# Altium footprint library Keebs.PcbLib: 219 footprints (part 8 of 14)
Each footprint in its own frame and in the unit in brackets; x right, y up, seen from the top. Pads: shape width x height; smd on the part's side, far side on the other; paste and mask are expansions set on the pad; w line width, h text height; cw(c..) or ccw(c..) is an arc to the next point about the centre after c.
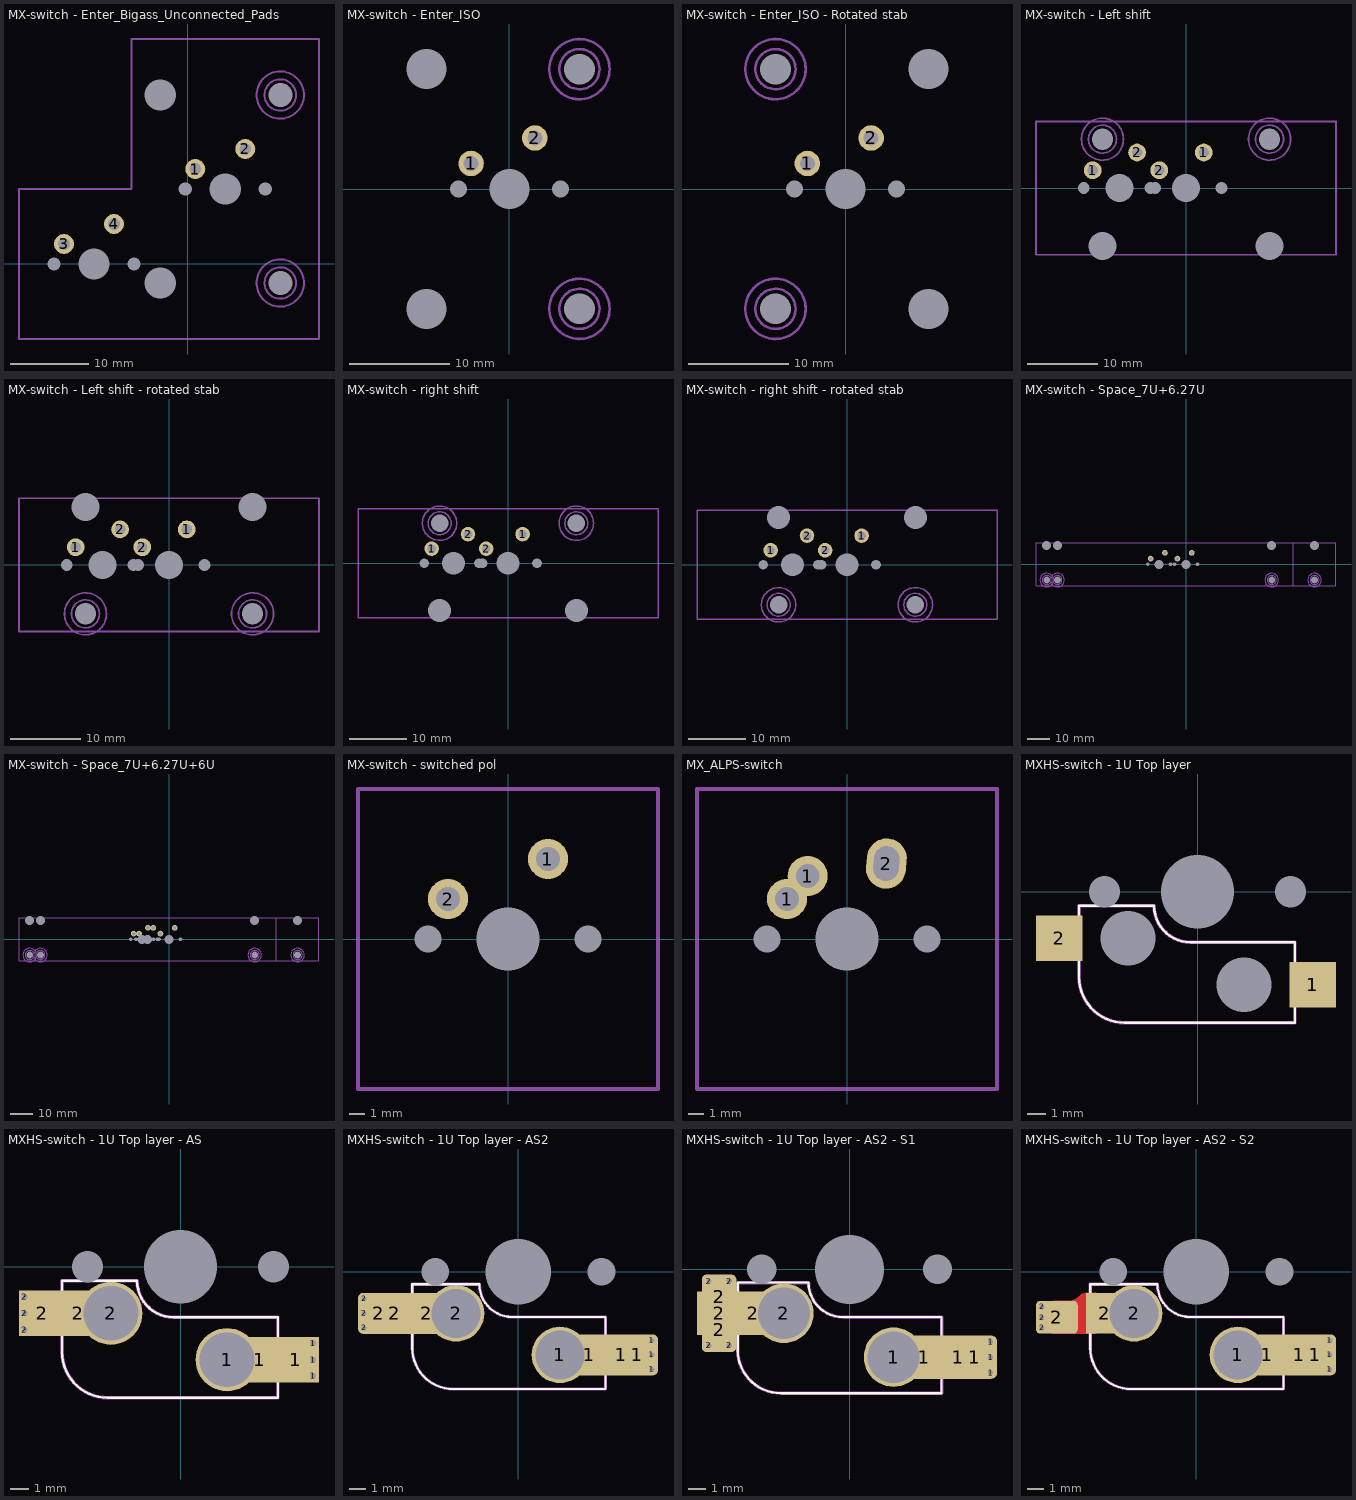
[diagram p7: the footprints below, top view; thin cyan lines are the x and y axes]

## MX-switch - Enter_Bigass_Unconnected_Pads [mm]
pads (20):
  round 2.54 hole 1.5 mask-0.5: 1(0.953,12.065) 2(7.302,14.605) 3(-15.716,2.54) 4(-9.366,5.08)
  round 1 hole 1.7 unplated: ""(-16.986,0) ""(-6.826,0) ""(-0.318,9.525) ""(9.842,9.525)
  round 1 hole 4 unplated: ""(-11.906,0) ""(4.763,9.525)
  round 1 on Mech13: ""(-11.906,0) ""(-11.906,0) ""(0,0) ""(0,0) ""(4.763,9.525) ""(4.763,9.525)
  round 1.524 hole 4 unplated: ""(-3.492,-2.413) ""(-3.492,21.463)
  round 1.524 hole 3.048 unplated: ""(11.747,-2.413) ""(11.747,21.463)
Mechanical 13:
  lines w0.254: -21.431,-9.525 -21.431,9.525 -7.144,9.525 -7.144,28.575 16.669,28.575 16.669,-9.525 -21.431,-9.525
  text ".Designator" at -3.683,-9.017 h0.7
Mechanical 15:
  circle w0.254: c11.747,21.463 r3
  circle w0.254: c11.747,21.463 r2
  circle w0.254: c11.747,-2.413 r3
  circle w0.254: c11.747,-2.413 r2

## MX-switch - Enter_ISO [mm]
pads (10):
  round 2.54 hole 1.5 mask-0.5: 1(-3.81,2.54) 2(2.54,5.08)
  round 1.524 hole 4 unplated: ""(-8.255,-11.938) ""(-8.255,11.938)
  round 1 hole 1.7 unplated: ""(-5.08,0) ""(5.08,0)
  round 1 hole 4 unplated: ""(0,0)
  round 1 on Mech13: ""(0,0)
  round 1.524 hole 3.048 unplated: ""(6.985,-11.938) ""(6.985,11.938)
Mechanical 13:
  text ".Designator" at -1.68,-7.73 h0.7
Mechanical 15:
  circle w0.254: c6.985,11.938 r3
  circle w0.254: c6.985,11.938 r2
  circle w0.254: c6.985,-11.938 r3
  circle w0.254: c6.985,-11.938 r2

## MX-switch - Enter_ISO - Rotated stab [mm]
pads (10):
  round 2.54 hole 1.5 mask-0.5: 1(-3.81,2.54) 2(2.54,5.08)
  round 1.524 hole 3.048 unplated: ""(-6.985,-11.938) ""(-6.985,11.938)
  round 1 hole 1.7 unplated: ""(-5.08,0) ""(5.08,0)
  round 1 hole 4 unplated: ""(0,0)
  round 1 on Mech13: ""(0,0)
  round 1.524 hole 4 unplated: ""(8.255,-11.938) ""(8.255,11.938)
Mechanical 13:
  text ".Designator" at -1.68,-7.73 h0.7
Mechanical 15:
  circle w0.254: c-6.985,-11.938 r3
  circle w0.254: c-6.985,-11.938 r2
  circle w0.254: c-6.985,11.938 r3
  circle w0.254: c-6.985,11.938 r2

## MX-switch - Left shift [mm]
pads (16):
  round 2.54 hole 1.5 mask-0.5: 1(-13.335,2.54) 1(2.54,5.08) 2(-6.985,5.08) 2(-3.81,2.54)
  round 1 hole 1.7 unplated: ""(-14.605,0) ""(-5.08,0) ""(-4.445,0) ""(5.08,0)
  round 1.524 hole 4 unplated: ""(-11.938,-8.255) ""(11.938,-8.255)
  round 1.524 hole 3.048 unplated: ""(-11.938,6.985) ""(11.938,6.985)
  round 1 hole 4 unplated: ""(-9.525,0) ""(0,0)
  round 1 on Mech13: ""(-9.525,0) ""(0,0)
Mechanical 13:
  lines w0.254: -21.431,-9.525 21.431,-9.525 21.431,9.525 -21.431,9.525 -21.431,-9.525
  text ".Designator" at -5.45,-3.925 h0.7
Mechanical 15:
  circle w0.254: c11.938,6.985 r3
  circle w0.254: c11.938,6.985 r2
  circle w0.254: c-11.938,6.985 r3
  circle w0.254: c-11.938,6.985 r2

## MX-switch - Left shift - rotated stab [mm]
pads (16):
  round 2.54 hole 1.5 mask-0.5: 1(-13.335,2.54) 1(2.54,5.08) 2(-6.985,5.08) 2(-3.81,2.54)
  round 1 hole 1.7 unplated: ""(-14.605,0) ""(-5.08,0) ""(-4.445,0) ""(5.08,0)
  round 1.524 hole 3.048 unplated: ""(-11.938,-6.985) ""(11.938,-6.985)
  round 1.524 hole 4 unplated: ""(-11.938,8.255) ""(11.938,8.255)
  round 1 hole 4 unplated: ""(-9.525,0) ""(0,0)
  round 1 on Mech13: ""(-9.525,0) ""(0,0)
Mechanical 13:
  lines w0.254: -21.431,-9.525 -21.431,9.525 21.431,9.525 21.431,-9.525 -21.431,-9.525
  text ".Designator" at -5.45,-3.925 h0.7
Mechanical 15:
  circle w0.254: c-11.938,-6.985 r2
  circle w0.254: c-11.938,-6.985 r3
  circle w0.254: c11.938,-6.985 r2
  circle w0.254: c11.938,-6.985 r3

## MX-switch - right shift [mm]
pads (16):
  round 2.54 hole 1.5 mask-0.5: 1(-13.335,2.54) 1(2.54,5.08) 2(-6.985,5.08) 2(-3.81,2.54)
  round 1 hole 1.7 unplated: ""(-14.605,0) ""(-5.08,0) ""(-4.445,0) ""(5.08,0)
  round 1.524 hole 4 unplated: ""(-11.938,-8.255) ""(11.938,-8.255)
  round 1.524 hole 3.048 unplated: ""(-11.938,6.985) ""(11.938,6.985)
  round 1 hole 4 unplated: ""(-9.525,0) ""(0,0)
  round 1 on Mech13: ""(-9.525,0) ""(0,0)
Mechanical 13:
  lines w0.254: -26.194,-9.525 26.194,-9.525 26.194,9.525 -26.194,9.525 -26.194,-9.525
  text ".Designator" at -4.3,-5.55 h0.7
Mechanical 15:
  circle w0.254: c11.938,6.985 r3
  circle w0.254: c11.938,6.985 r2
  circle w0.254: c-11.938,6.985 r3
  circle w0.254: c-11.938,6.985 r2

## MX-switch - right shift - rotated stab [mm]
pads (16):
  round 2.54 hole 1.5 mask-0.5: 1(-13.335,2.54) 1(2.54,5.08) 2(-6.985,5.08) 2(-3.81,2.54)
  round 1 hole 1.7 unplated: ""(-14.605,0) ""(-5.08,0) ""(-4.445,0) ""(5.08,0)
  round 1.524 hole 3.048 unplated: ""(-11.938,-6.985) ""(11.938,-6.985)
  round 1.524 hole 4 unplated: ""(-11.938,8.255) ""(11.938,8.255)
  round 1 hole 4 unplated: ""(-9.525,0) ""(0,0)
  round 1 on Mech13: ""(-9.525,0) ""(0,0)
Mechanical 13:
  lines w0.254: -26.194,-9.525 -26.194,9.525 26.194,9.525 26.194,-9.525 -26.194,-9.525
  text ".Designator" at -4.3,-5.55 h0.7
Mechanical 15:
  circle w0.254: c11.938,-6.985 r3
  circle w0.254: c11.938,-6.985 r2
  circle w0.254: c-11.938,-6.985 r3
  circle w0.254: c-11.938,-6.985 r2

## MX-switch - Space_7U+6.27U [mm]
pads (20):
  round 2.54 hole 1.5 mask-0.5: 1(-9.366,5.08) 1(-3.81,2.54) 2(-15.716,2.54) 2(2.54,5.08)
  round 1.524 hole 3.048 unplated: ""(-61.91,-6.985) ""(-57.15,-6.985) ""(38.09,-6.985) ""(57.15,-6.985)
  round 1.524 hole 4 unplated: ""(-61.91,8.255) ""(-57.15,8.255) ""(38.09,8.255) ""(57.15,8.255)
  round 1 hole 1.7 unplated: ""(-16.986,0) ""(-6.826,0) ""(-5.08,0) ""(5.08,0)
  round 1 hole 4 unplated: ""(-11.906,0) ""(0,0)
  round 1 on Mech13: ""(-11.906,0) ""(0,0)
Mechanical 13:
  lines w0.254: 47.621,-9.525 47.621,9.525 ; -66.675,-9.525 -66.675,9.525 66.675,9.525 66.675,-9.525 -66.675,-9.525
  text ".Designator" at 7.625,-2.4 h0.7
Mechanical 15:
  circle w0.254: c57.15,-6.985 r3
  circle w0.254: c57.15,-6.985 r2
  circle w0.254: c38.09,-6.985 r3
  circle w0.254: c38.09,-6.985 r2
  circle w0.254: c-57.15,-6.985 r3
  circle w0.254: c-57.15,-6.985 r2
  circle w0.254: c-61.91,-6.985 r3
  circle w0.254: c-61.91,-6.985 r2
  text "7U" at 65.831,-1.85 h1.52
  text "6.25U" at 46.265,-3.6 h1.52

## MX-switch - Space_7U+6.27U+6U [mm]
pads (25):
  round 2.54 hole 1.5 mask-0.5: 1(-9.366,5.08) 1(-6.981,5.08) 1(-3.81,2.54) 2(-15.716,2.54) 2(-13.331,2.54) 2(2.54,5.08)
  round 1.524 hole 3.048 unplated: ""(-61.91,-6.985) ""(-57.15,-6.985) ""(38.09,-6.985) ""(57.15,-6.985)
  round 1.524 hole 4 unplated: ""(-61.91,8.255) ""(-57.15,8.255) ""(38.09,8.255) ""(57.15,8.255)
  round 1 hole 1.7 unplated: ""(-16.986,0) ""(-14.601,0) ""(-6.826,0) ""(-5.08,0) ""(-4.441,0) ""(5.08,0)
  round 1 hole 4 unplated: ""(-11.906,0) ""(-9.521,0) ""(0,0)
  round 1 on Mech13: ""(-11.906,0) ""(0,0)
Mechanical 13:
  lines w0.254: 47.621,-9.525 47.621,9.525 ; -66.675,-9.525 -66.675,9.525 66.675,9.525 66.675,-9.525 -66.675,-9.525
  text ".Designator" at 7.625,-2.4 h0.7
Mechanical 15:
  circle w0.254: c57.15,-6.985 r3
  circle w0.254: c57.15,-6.985 r2
  circle w0.254: c38.09,-6.985 r3
  circle w0.254: c38.09,-6.985 r2
  circle w0.254: c-57.15,-6.985 r3
  circle w0.254: c-57.15,-6.985 r2
  circle w0.254: c-61.91,-6.985 r3
  circle w0.254: c-61.91,-6.985 r2
  text "7U" at 65.831,-1.85 h1.52
  text "6.25U" at 46.265,-3.6 h1.52

## MX-switch - switched pol [mm]
pads (5):
  round 2.54 hole 1.5 mask-0.5: 1(2.54,5.08) 2(-3.81,2.54)
  round 1 hole 1.7 unplated: ""(-5.08,0) ""(5.08,0)
  round 1 hole 4 unplated: ""(0,0)
Mechanical 13:
  lines w0.254: -9.525,-9.525 9.525,-9.525 9.525,9.525 -9.525,9.525 -9.525,-9.525
  text ".Designator" at -3.575,-3.7 h0.7

## MX_ALPS-switch [mm]
pads (6):
  round 2.54 hole 1.5 mask-0.5: 1(-3.81,2.54) 1(-2.5,4)
  oval 3.2x2.54 hole 1.6 slot 2.2 at 85 deg rot 85 mask-1: 2(2.5,4.79)
  round 1 hole 1.7 unplated: ""(-5.08,0) ""(5.08,0)
  round 1 hole 4 unplated: ""(0,0)
Mechanical 13:
  lines w0.254: -9.525,-9.525 9.525,-9.525 9.525,9.525 -9.525,9.525 -9.525,-9.525
  text ".Designator" at -3.575,-3.7 h0.7

## MXHS-switch - 1U Top layer [mm]
pads (7):
  rect 2.55x2.5 smd: 1(6.29,-5.08) 2(-7.56,-2.54)
  round 1 hole 1.7 unplated: ""(-5.08,0) ""(5.08,0)
  round 0 hole 3 unplated: ""(-3.81,-2.54) ""(2.54,-5.08)
  round 1 hole 4 unplated: ""(0,0)
Top Overlay:
  lines w0.127: -6.481,-4.662 ccw(c-3.981,-4.662) -3.981,-7.162 5.319,-7.162 5.319,-2.762 -0.381,-2.762 cw(c-0.381,-0.762) -2.381,-0.762 -6.481,-0.762 -6.481,-4.662
Mechanical 13:
  lines w0.1: -0.5,0 0.5,0 ; 0,-0.5 0,0.5
  lines w0.2: -6.481,-4.662 ccw(c-3.981,-4.662) -3.981,-7.162 5.319,-7.162 5.319,-2.762 -0.381,-2.762 cw(c-0.381,-0.762) -2.381,-0.762 -6.481,-0.762 -6.481,-4.662
  text ".Designator" at 3.048,-4.826 h0.7
Mechanical 15:
  lines w0.1: -1.77,0 -0.77,0 ; 0,-0.5 0,0.5
  lines w0.127: -6.481,-4.662 ccw(c-3.981,-4.662) -3.981,-7.162 5.319,-7.162 5.319,-2.762 -0.381,-2.762 cw(c-0.381,-0.762) -2.381,-0.762 -6.481,-0.762 -6.481,-4.662
3D body "kailh_socket_mx.stp": height -0.35, standoff -3.4, extent -7.9,-6.745 6.6,-0.855

## MXHS-switch - 1U Top layer - AS [mm]
pads (15):
  round 3.45 hole 3 mask+0: 1(2.54,-5.08) 2(-3.81,-2.54)
  rect 2.55x2.5 smd paste-40 mask+0.102: 1(4.318,-5.08) 2(-5.588,-2.54)
  rect 2.55x2.5 smd: 1(6.29,-5.08) 2(-7.56,-2.54)
  round 0.6 hole 0.3 mask+0.102: 1(7.25,-5.969) 1(7.25,-5.08) 1(7.25,-4.191) 2(-8.52,-3.429) 2(-8.52,-2.54) 2(-8.52,-1.651)
  round 1 hole 1.7 unplated: ""(-5.08,0) ""(5.08,0)
  round 1 hole 4 unplated: ""(0,0)
Top Overlay:
  lines w0.127: -6.481,-4.662 ccw(c-3.981,-4.662) -3.981,-7.162 5.319,-7.162 5.319,-2.762 -0.381,-2.762 cw(c-0.381,-0.762) -2.381,-0.762 -6.481,-0.762 -6.481,-4.662
Mechanical 13:
  lines w0.1: -0.5,0 0.5,0 ; 0,-0.5 0,0.5
  lines w0.2: -6.481,-4.662 ccw(c-3.981,-4.662) -3.981,-7.162 5.319,-7.162 5.319,-2.762 -0.381,-2.762 cw(c-0.381,-0.762) -2.381,-0.762 -6.481,-0.762 -6.481,-4.662
  text ".Designator" at 3.048,-4.826 h0.7
Mechanical 15:
  lines w0.1: -1.77,0 -0.77,0 ; 0,-0.5 0,0.5
  lines w0.127: -6.481,-4.662 ccw(c-3.981,-4.662) -3.981,-7.162 5.319,-7.162 5.319,-2.762 -0.381,-2.762 cw(c-0.381,-0.762) -2.381,-0.762 -6.481,-0.762 -6.481,-4.662
3D body "kailh_socket_mx.stp": height -0.35, standoff -3.4, extent -7.9,-6.745 6.6,-0.855

## MXHS-switch - 1U Top layer - AS2 [mm]
pads (17):
  round 3.45 hole 3 mask+0: 1(2.54,-5.08) 2(-3.81,-2.54)
  rect 2.55x2.5 smd paste-40 mask+0.102: 1(4.318,-5.08) 2(-5.588,-2.54)
  rect 2.55x2.5 smd: 1(6.29,-5.08) 2(-7.56,-2.54)
  rrect25% 2.55x2.5 smd paste-40 mask+0.102: 1(7.25,-5.08) 2(-8.52,-2.54)
  round 0.6 hole 0.3 mask+0.102: 1(8.15,-5.969) 1(8.15,-5.08) 1(8.15,-4.191) 2(-9.42,-3.429) 2(-9.42,-2.54) 2(-9.42,-1.651)
  round 1 hole 1.7 unplated: ""(-5.08,0) ""(5.08,0)
  round 1 hole 4 unplated: ""(0,0)
Top Overlay:
  lines w0.127: -6.481,-4.662 ccw(c-3.981,-4.662) -3.981,-7.162 5.319,-7.162 5.319,-2.762 -0.381,-2.762 cw(c-0.381,-0.762) -2.381,-0.762 -6.481,-0.762 -6.481,-4.662
Mechanical 13:
  lines w0.1: -0.5,0 0.5,0 ; 0,-0.5 0,0.5
  lines w0.2: -6.481,-4.662 ccw(c-3.981,-4.662) -3.981,-7.162 5.319,-7.162 5.319,-2.762 -0.381,-2.762 cw(c-0.381,-0.762) -2.381,-0.762 -6.481,-0.762 -6.481,-4.662
  text ".Designator" at 3.048,-4.826 h0.7
Mechanical 15:
  lines w0.1: -1.77,0 -0.77,0 ; 0,-0.5 0,0.5
  lines w0.127: -6.481,-4.662 ccw(c-3.981,-4.662) -3.981,-7.162 5.319,-7.162 5.319,-2.762 -0.381,-2.762 cw(c-0.381,-0.762) -2.381,-0.762 -6.481,-0.762 -6.481,-4.662
3D body "kailh_socket_mx.stp": height -0.35, standoff -3.4, extent -7.9,-6.745 6.6,-0.855

## MXHS-switch - 1U Top layer - AS2 - S1 [mm]
pads (19):
  round 3.45 hole 3 mask+0: 1(2.54,-5.08) 2(-3.81,-2.54)
  rect 2.55x2.5 smd paste-40 mask+0.102: 1(4.318,-5.08) 2(-5.588,-2.54)
  rect 2.55x2.5 smd: 1(6.29,-5.08) 2(-7.56,-2.54)
  rrect25% 2.55x2.5 smd paste-40 mask+0.102: 1(7.25,-5.08)
  round 0.6 hole 0.3 mask+0.102: 1(8.15,-5.969) 1(8.15,-5.08) 1(8.15,-4.191) 2(-8.149,-4.4) 2(-8.149,-0.68) 2(-6.971,-4.4) 2(-6.971,-0.68)
  rrect25% 2x2.55 smd paste-40 mask+0.102: 2(-7.56,-3.5) 2(-7.56,-1.58)
  round 1 hole 1.7 unplated: ""(-5.08,0) ""(5.08,0)
  round 1 hole 4 unplated: ""(0,0)
Top Overlay:
  lines w0.127: -6.481,-4.662 ccw(c-3.981,-4.662) -3.981,-7.162 5.319,-7.162 5.319,-2.762 -0.381,-2.762 cw(c-0.381,-0.762) -2.381,-0.762 -6.481,-0.762 -6.481,-4.662
Mechanical 13:
  lines w0.1: -0.5,0 0.5,0 ; 0,-0.5 0,0.5
  lines w0.2: -6.481,-4.662 ccw(c-3.981,-4.662) -3.981,-7.162 5.319,-7.162 5.319,-2.762 -0.381,-2.762 cw(c-0.381,-0.762) -2.381,-0.762 -6.481,-0.762 -6.481,-4.662
  text ".Designator" at 3.048,-4.826 h0.7
Mechanical 15:
  lines w0.1: -1.77,0 -0.77,0 ; 0,-0.5 0,0.5
  lines w0.127: -6.481,-4.662 ccw(c-3.981,-4.662) -3.981,-7.162 5.319,-7.162 5.319,-2.762 -0.381,-2.762 cw(c-0.381,-0.762) -2.381,-0.762 -6.481,-0.762 -6.481,-4.662
3D body "kailh_socket_mx.stp": height -0.35, standoff -3.4, extent -7.9,-6.745 6.6,-0.855

## MXHS-switch - 1U Top layer - AS2 - S2 [mm] "Adjusted footprint to prevent conflict with tray mount mounting hole"
pads (16):
  round 3.45 hole 3 mask+0: 1(2.54,-5.08) 2(-3.81,-2.54)
  rect 2.55x2.5 smd paste-40 mask+0.102: 1(4.318,-5.08)
  rect 2.55x2.5 smd: 1(6.29,-5.08)
  rrect25% 2.55x2.5 smd paste-40 mask+0.102: 1(7.25,-5.08)
  round 0.6 hole 0.3 mask+0.102: 1(8.15,-5.969) 1(8.15,-5.08) 1(8.15,-4.191) 2(-9.42,-3.429) 2(-9.42,-2.795) 2(-9.42,-2.15)
  rrect25% 2.55x2 smd paste-40 mask+0.102: 2(-8.52,-2.78)
  rect 2.3x2.492 smd paste-40 mask+0.102: 2(-5.588,-2.54)
  round 1 hole 1.7 unplated: ""(-5.08,0) ""(5.08,0)
  round 1 hole 4 unplated: ""(0,0)
Top Layer:
  region: -6.121,-1.295 -6.121,-3.785 -8.839,-3.785 -8.839,-1.905 -8.839,-1.88 -8.82,-1.833 -8.784,-1.797 -8.737,-1.778 -8.712,-1.778 -7.891,-1.778 -7.785,-1.773 -7.577,-1.731 -7.38,-1.65 -7.204,-1.532 -7.125,-1.46 -7.085,-1.421 -6.993,-1.36 -6.891,-1.317 -6.782,-1.295 -6.726,-1.295
Top Overlay:
  lines w0.127: -6.481,-4.662 ccw(c-3.981,-4.662) -3.981,-7.162 5.319,-7.162 5.319,-2.762 -0.381,-2.762 cw(c-0.381,-0.762) -2.381,-0.762 -6.481,-0.762 -6.481,-4.662
Mechanical 13:
  lines w0.1: -0.5,0 0.5,0 ; 0,-0.5 0,0.5
  lines w0.2: -6.481,-4.662 ccw(c-3.981,-4.662) -3.981,-7.162 5.319,-7.162 5.319,-2.762 -0.381,-2.762 cw(c-0.381,-0.762) -2.381,-0.762 -6.481,-0.762 -6.481,-4.662
  text ".Designator" at 3.048,-4.826 h0.7
Mechanical 15:
  lines w0.1: -1.77,0 -0.77,0 ; 0,-0.5 0,0.5
  lines w0.127: -6.481,-4.662 ccw(c-3.981,-4.662) -3.981,-7.162 5.319,-7.162 5.319,-2.762 -0.381,-2.762 cw(c-0.381,-0.762) -2.381,-0.762 -6.481,-0.762 -6.481,-4.662
3D body "kailh_socket_mx.stp": height -0.35, standoff -3.4, extent -7.9,-6.745 6.6,-0.855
